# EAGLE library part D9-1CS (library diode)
8 DIODES SIL, common cathode (single gate)
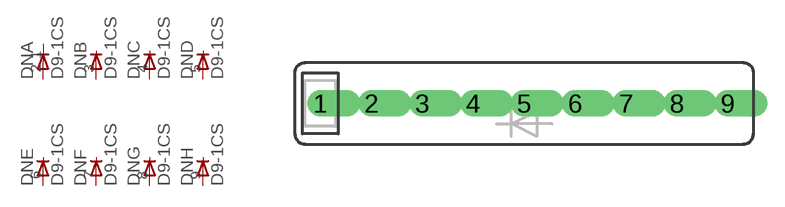
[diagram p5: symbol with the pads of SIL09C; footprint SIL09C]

Designator prefix DN; gates A=DN B=DNC C=DNC D=DNC E=DNC F=DNC G=DNC H=DNC

## D9-1CS  [SIL09C]
1  A:C  pas
2  A:A  pas
3  B:A  pas
4  C:A  pas
5  D:A  pas
6  E:A  pas
7  F:A  pas
8  G:A  pas
9  H:A  pas

## Footprint SIL09C (pad centres in mm)
8 DIODES single in line 8 diodes with common cathode
drill 0.813 offset: 1 -10.16,0; 2 -7.62,0; 3 -5.08,0; 4 -2.54,0; 5 0,0; 6 2.54,0; 7 5.08,0; 8 7.62,0; 9 10.16,0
